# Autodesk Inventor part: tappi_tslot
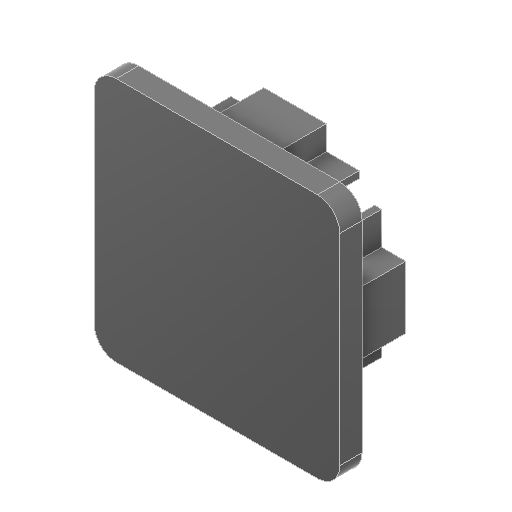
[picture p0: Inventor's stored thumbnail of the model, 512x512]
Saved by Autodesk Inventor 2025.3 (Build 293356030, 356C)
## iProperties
Created: 2025-05
Part Number: tappi_tslot
Material: Plastica ABS
Document SubType Name: Modeling
Designer: R5800u
Density: 1.06 g/cm^3
Appearance: Liscia - Nero
Author: R5800u
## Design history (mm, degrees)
sketch "Schizzo1"
  geometry: L1 (-10, -10)-(10, -10); L2 (10, -10)-(10, 10); L3 (10, 10)-(-10, 10); L4 (-10, 10)-(-10, -10); L5 (-10, -10)-(10, 10); L6 (10, -10)-(-10, 10); 1 further point
  constraints: 12 end point, 2 midpoint, 2 parallel, 1 horizontal, 1 perpendicular
  dimensions: "d0" = 20 distance of L3.end L2.end; "d1" = 20 distance of L2.end L1.end
extrude "Estrusione1" new body sketch "Schizzo1" distance "d2" = 2; taper "d3" = 0 deg
sketch "Schizzo3"
  geometry: L1 (-10, -10)-(-10, 10) reference; L2 (-7.84, -2.898)-(-7.84, -5.843); L3 (-7.84, -5.843)-(-7.082, -5.843); L4 (-7.082, -5.843)-(-4.099, -2.898); L5 (-4.099, -2.898)-(-4.099, 0); L6 (-4.099, 0)-(-10, 0); L7 (-10, -2.898)-(-10, 0); L8 (-10, 2.898)-(-7.84, 2.898); L9 (-7.84, 2.898)-(-7.84, 5.843); L10 (-7.84, 5.843)-(-7.082, 5.843); L11 (-7.082, 5.843)-(-4.099, 2.898); L12 (-4.099, 2.898)-(-4.099, 0); L13 (-10, 2.898)-(-10, 0); L14 (-4.199, 0)-(-4.199, 2.857); L15 (-4.199, 2.857)-(-7.123, 5.743); L16 (-7.123, 5.743)-(-7.74, 5.743); L17 (-7.74, 5.743)-(-7.74, 2.798); L18 (-7.74, 2.798)-(-9.9, 2.798); L19 (-9.9, 2.798)-(-9.9, 0); L20 (-4.199, 0)-(-4.199, -2.857); L21 (-4.199, -2.857)-(-7.123, -5.743); L22 (-7.123, -5.743)-(-7.74, -5.743); L23 (-7.74, -5.743)-(-7.74, -2.798); L24 (-7.74, -2.798)-(-9.9, -2.798); L25 (-9.9, -2.798)-(-9.9, 0); L26 (-5.743, -7.123)-(-5.743, -7.74); L27 (-5.843, -7.84)-(-5.843, -7.082); L28 (-2.898, -10)-(-2.898, -7.84); L29 (-2.898, -7.84)-(-5.843, -7.84); L30 (-2.798, -7.74)-(-2.798, -9.9); L31 (-5.743, -7.74)-(-2.798, -7.74); L32 (-2.857, -4.199)-(-5.743, -7.123); L33 (-5.843, -7.082)-(-2.898, -4.099); L34 (-2.798, -9.9)-(0, -9.9); L35 (-2.898, -10)-(0, -10); L36 (0, -4.199)-(-2.857, -4.199); L37 (0, -4.099)-(0, -10); L38 (-2.898, -4.099)-(0, -4.099); L39 (2.898, -7.84)-(5.843, -7.84); L40 (5.843, -7.84)-(5.843, -7.082); L41 (5.843, -7.082)-(2.898, -4.099); L42 (2.898, -4.099)-(0, -4.099); L43 (2.898, -10)-(0, -10); L44 (0, -4.199)-(2.857, -4.199); L45 (2.798, -9.9)-(0, -9.9); L46 (2.798, -7.74)-(2.798, -9.9); L47 (2.857, -4.199)-(5.743, -7.123); L48 (5.743, -7.123)-(5.743, -7.74); L49 (5.743, -7.74)-(2.798, -7.74); L50 (7.123, -5.743)-(7.74, -5.743); L51 (7.84, -5.843)-(7.082, -5.843); L52 (10, -2.898)-(7.84, -2.898); L53 (7.84, -2.898)-(7.84, -5.843); L54 (7.74, -2.798)-(9.9, -2.798); L55 (7.74, -5.743)-(7.74, -2.798); L56 (4.199, -2.857)-(7.123, -5.743); L57 (7.082, -5.843)-(4.099, -2.898); L58 (9.9, -2.798)-(9.9, 0); L59 (10, -2.898)-(10, 0); L60 (4.199, 0)-(4.199, -2.857); L61 (4.099, 0)-(10, 0); L62 (4.099, -2.898)-(4.099, 0); L63 (7.84, 2.898)-(7.84, 5.843); L64 (7.84, 5.843)-(7.082, 5.843)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; C1 r 2 at (0, 0); 10 further points
  constraints: 192 end point, 5 point on line, 5 symmetric about line, 3 perpendicular, 2 parallel, 1 centre point, 1 coincident, 1 collinear, 1 midpoint, 209 other
  dimensions: "d5" = 4 diameter of C1; "d12" = 0.1 distance between parallel lines of L11 L15; "d16" = 360 deg dimension on point (0, 0) L15.end (derived)
extrude "Estrusione2" join sketch "Schizzo3" distance "d6" = 5; taper "d7" = 0 deg
sketch "Schizzo4"
  geometry: L1 (11, 11)-(-11, 11); L2 (-11, 11)-(-11, -11); L3 (-11, -11)-(11, -11); L4 (11, -11)-(11, 11); L5 (11, 11)-(-11, -11); L6 (-11, 11)-(11, -11); L7 (10, -10)-(10, 10) reference; L8 (10, 10)-(-10, 10) reference; L9 (-10, 10)-(-10, -10) reference; L10 (-10, -10)-(10, -10) reference; 1 further point
  constraints: 12 end point, 2 midpoint, 2 parallel, 1 horizontal, 1 perpendicular
  dimensions: "d18" = 22 distance of L3.end L2.end; "d19" = 22 distance of L2.end L1.end
extrude "Estrusione3" join sketch "Schizzo4" stored distance "d20" = 5; taper "d21" = 0 deg
fillet "Raccordo1" dims "d22" = 2
node "Solido1"
node "Schizzo - Serie circolare2" dims "d16" = 360 deg (derived)
node "Linea chiusa proiettata1"
